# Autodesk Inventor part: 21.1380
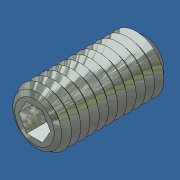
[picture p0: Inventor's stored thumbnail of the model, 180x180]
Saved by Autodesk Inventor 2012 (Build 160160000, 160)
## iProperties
Created: 2011-09
Part Number: 21.1380
Document SubType Name: Modeling
Designer: Administrator
Density: 7.85 g/cm^3
Mass: 1.90208 g
Surface Area: 3.80676 cm^2
Volume: 0.242304 cm^3
Material: Alloy Steel
Description: M6X12 SET SCREW FLAT END
Vendor: S
Author: Administrator
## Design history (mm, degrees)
feature "Base1"
body "Solid1"
